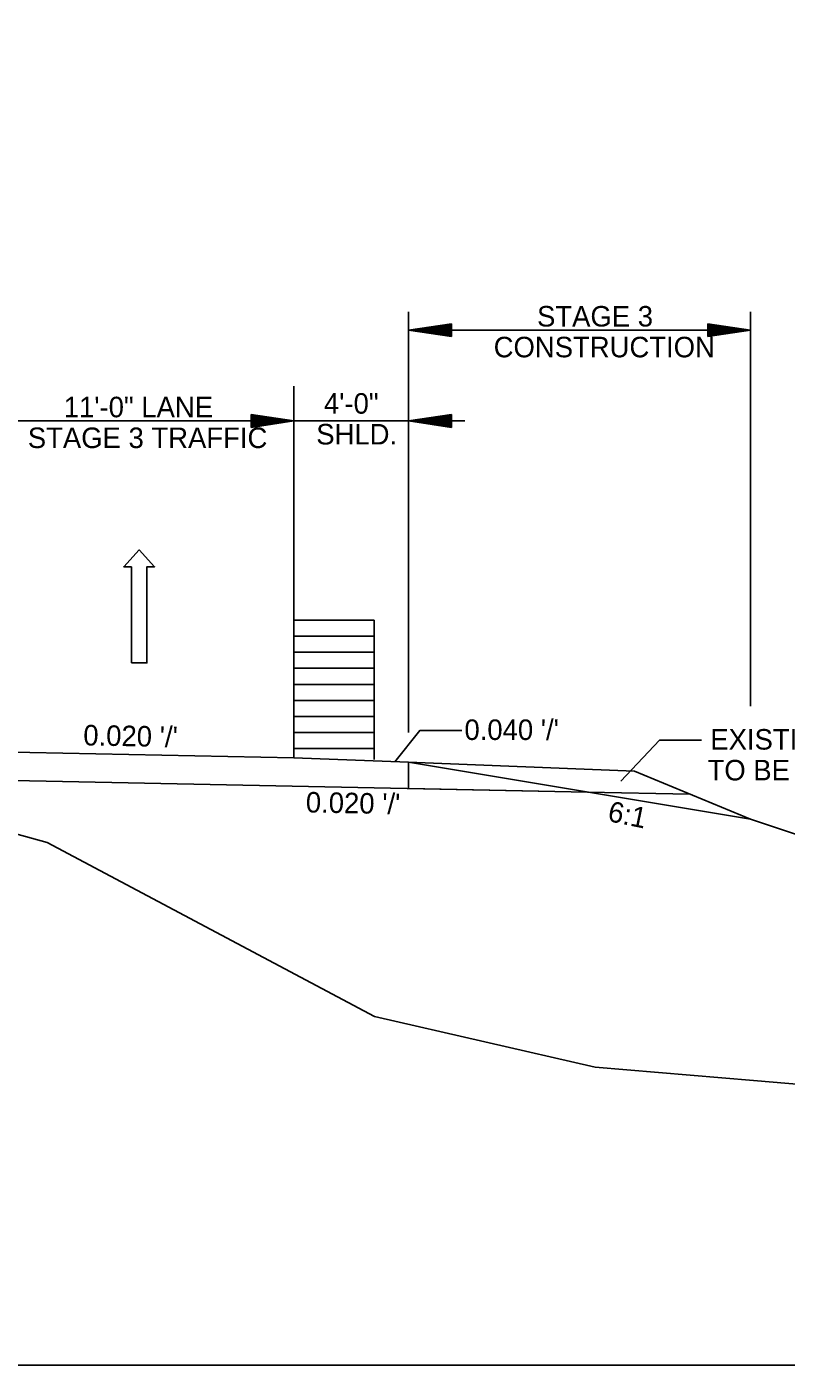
# Model space of a CAD drawing. Extents: x 1807779 to 1818251, y 673292 to 678849.
# Drawn here: x 1813605.8 to 1813872, y 676379.9 to 676849.3 of the extents above; entities that cross this region are included whole.
import ezdxf

# ---------------------------------------------------------------- set-up
doc = ezdxf.new("R2010")
doc.units = 0
for name, color, linetype in [('Default', 7, 'Continuous'), ('Dimensions', 7, 'Continuous'), ('DSN_DRFT_Guideline-No-Plot', 7, 'Continuous'), ('EX_DRIVEWAY', 7, 'Continuous'), ('EX_TERRAIN', 7, 'Continuous'), ('R_MOT', 7, 'Continuous')]:
    doc.layers.add(name, color=color, linetype=linetype)

msp = doc.modelspace()

# ---------------------------------------------------------------- linework, layer by layer
at = {"layer": 'Default'}
for p, q in [((1813699.41, 676641.2), (1813699.41, 676592.98)), ((1813727.53, 676641.2), (1813699.41, 676641.2)), ((1813727.53, 676592.29), (1813727.53, 676641.2)), ((1813727.53, 676635.58), (1813699.41, 676635.58)), ((1813727.53, 676629.95), (1813727.53, 676635.58)), ((1813699.41, 676629.95), (1813727.53, 676629.95)), ((1813699.41, 676624.33), (1813727.53, 676624.33)), ((1813699.41, 676618.7), (1813699.41, 676624.33)), ((1813727.53, 676618.7), (1813699.41, 676618.7)), ((1813699.41, 676613.08), (1813727.53, 676613.08)), ((1813699.41, 676607.45), (1813699.41, 676613.08)), ((1813727.53, 676607.45), (1813699.41, 676607.45)), ((1813727.53, 676601.83), (1813699.41, 676601.83)), ((1813727.53, 676596.2), (1813727.53, 676601.83)), ((1813699.41, 676596.2), (1813727.53, 676596.2)), ((1813739.66, 676591.37), (1813739.66, 676582.17)), ((1813739.66, 676582.17), (1813802.36, 676580.92))]:
    msp.add_line(p, q, dxfattribs=at)
at = {"layer": 'Dimensions'}
for p, q in [((1813739.66, 676723.25), (1813739.66, 676749.35)), ((1813859.54, 676611), (1813859.54, 676749.35)), ((1813754.66, 676745.16), (1813739.66, 676742.91)), ((1813754.66, 676744.78), (1813742.17, 676742.91)), ((1813754.66, 676744.4), (1813744.75, 676742.91)), ((1813754.66, 676744.03), (1813747.24, 676742.91)), ((1813754.66, 676740.66), (1813754.66, 676745.16)), ((1813844.54, 676745.16), (1813859.54, 676742.91)), ((1813844.54, 676740.66), (1813844.54, 676745.16)), ((1813844.54, 676744.78), (1813857.03, 676742.91)), ((1813844.54, 676744.4), (1813854.45, 676742.91)), ((1813844.54, 676744.03), (1813851.95, 676742.91)), ((1813859.54, 676742.91), (1813739.66, 676742.91)), ((1813754.66, 676740.66), (1813739.66, 676742.91)), ((1813754.66, 676741.03), (1813742.17, 676742.91)), ((1813754.66, 676741.42), (1813744.75, 676742.91)), ((1813754.66, 676741.79), (1813747.24, 676742.91)), ((1813754.66, 676743.64), (1813749.79, 676742.91)), ((1813754.66, 676742.18), (1813749.79, 676742.91)), ((1813754.66, 676743.26), (1813752.29, 676742.91)), ((1813754.66, 676742.56), (1813752.29, 676742.91)), ((1813844.54, 676743.64), (1813849.41, 676742.91)), ((1813844.54, 676743.26), (1813846.91, 676742.91)), ((1813844.54, 676740.66), (1813859.54, 676742.91)), ((1813844.54, 676742.18), (1813849.41, 676742.91)), ((1813844.54, 676741.42), (1813854.45, 676742.91)), ((1813844.54, 676741.03), (1813857.03, 676742.91)), ((1813844.54, 676741.79), (1813851.95, 676742.91)), ((1813844.54, 676742.56), (1813846.91, 676742.91)), ((1813699.43, 676601.76), (1813699.43, 676723.25)), ((1813739.66, 676601.76), (1813739.66, 676723.25)), ((1813589.43, 676711.08), (1813648.86, 676711.08)), ((1813589.43, 676711.08), (1813699.43, 676711.08)), ((1813684.43, 676713.33), (1813699.43, 676711.08)), ((1813684.43, 676708.83), (1813684.43, 676713.33)), ((1813684.43, 676712.95), (1813696.93, 676711.08)), ((1813684.43, 676712.57), (1813694.35, 676711.08)), ((1813684.43, 676712.19), (1813691.85, 676711.08)), ((1813684.43, 676711.81), (1813689.31, 676711.08)), ((1813684.43, 676711.43), (1813686.8, 676711.08)), ((1813684.43, 676708.83), (1813699.43, 676711.08)), ((1813684.43, 676710.35), (1813689.31, 676711.08)), ((1813684.43, 676709.58), (1813694.35, 676711.08)), ((1813684.43, 676709.2), (1813696.93, 676711.08)), ((1813684.43, 676709.96), (1813691.85, 676711.08)), ((1813684.43, 676710.72), (1813686.8, 676711.08)), ((1813699.43, 676711.08), (1813759.3, 676711.08)), ((1813754.66, 676713.33), (1813739.66, 676711.08)), ((1813754.66, 676708.83), (1813739.66, 676711.08)), ((1813754.66, 676712.95), (1813742.17, 676711.08)), ((1813754.66, 676709.2), (1813742.17, 676711.08)), ((1813754.66, 676712.57), (1813744.75, 676711.08)), ((1813754.66, 676709.58), (1813744.75, 676711.08)), ((1813754.66, 676712.19), (1813747.24, 676711.08)), ((1813754.66, 676709.96), (1813747.24, 676711.08)), ((1813754.66, 676711.81), (1813749.79, 676711.08)), ((1813754.66, 676710.35), (1813749.79, 676711.08)), ((1813754.66, 676711.43), (1813752.29, 676711.08)), ((1813754.66, 676710.72), (1813752.29, 676711.08)), ((1813754.66, 676708.83), (1813754.66, 676713.33)), ((1813642.46, 676626.19), (1813642.46, 676659.92))]:
    msp.add_line(p, q, dxfattribs=at)
for points in [[(1813642.46, 676626.19), (1813647.86, 676626.19), (1813647.86, 676659.92), (1813650.56, 676659.92), (1813645.16, 676665.84), (1813639.76, 676659.92), (1813642.46, 676659.92)], [(1813734.77, 676591.56), (1813743.57, 676602.48), (1813758.3, 676602.48)], [(1813814.01, 676584.72), (1813827.63, 676599.12), (1813842.37, 676599.12)]]:
    msp.add_lwpolyline(points, dxfattribs=at)
at = {"layer": 'DSN_DRFT_Guideline-No-Plot'}
msp.add_lwpolyline([(1812650.63, 676379.88), (1814300.63, 676379.88), (1814300.63, 677378.94), (1812650.63, 677378.94)], close=True, dxfattribs=at)
at = {"layer": 'EX_DRIVEWAY'}
for p, q in [((1813589.43, 676595.18), (1813699.41, 676592.98)), ((1813699.41, 676592.98), (1813739.66, 676591.37)), ((1813589.43, 676585.18), (1813802.36, 676580.92)), ((1813859.54, 676571.39), (1814149.89, 676474.61))]:
    msp.add_line(p, q, dxfattribs=at)
at = {"layer": 'EX_TERRAIN'}
for p, q in [((1813739.66, 676591.37), (1813818.83, 676588.2)), ((1813818.83, 676588.2), (1813859.54, 676571.39)), ((1813802.36, 676580.92), (1813838.2, 676580.2))]:
    msp.add_line(p, q, dxfattribs=at)
msp.add_lwpolyline([(1812677.73, 676590.75), (1812733.39, 676557.8), (1812876.78, 676502.56), (1812958.07, 676504.7), (1813052.65, 676556.13), (1813143.36, 676593.92), (1813217.94, 676596.07), (1813298.12, 676597.14), (1813458.11, 676595), (1813486.58, 676594.36), (1813514.91, 676590.77), (1813565.47, 676576.34), (1813612.93, 676563.25), (1813727.64, 676502.24), (1813805.09, 676484.4), (1813860.58, 676479.74), (1813917.03, 676474.91), (1814103.84, 676473.94), (1814245.64, 676472.02)], dxfattribs=at)
at = {"layer": 'R_MOT'}
msp.add_line((1813739.66, 676591.37), (1813859.54, 676571.39), dxfattribs=at)

# ---------------------------------------------------------------- texts
at = {"layer": 'Dimensions'}
for s, p in [('STAGE 3 ', (1813784.67, 676744.2)), ('CONSTRUCTION', (1813769.47, 676733.4)), ('4\'-0" ', (1813709.95, 676713.63)), ('11\'-0" LANE', (1813618.72, 676712.37)), ('STAGE 3 TRAFFIC', (1813606.12, 676701.57)), ('SHLD. ', (1813707.26, 676702.83))]:
    msp.add_text(s, height=7.2, dxfattribs=at).set_placement(p)
for s, rotation, p in [("0.020 '/'", 358.8777, (1813625.52, 676597.31)), ("0.040 '/'", 360, (1813759.22, 676599.18)), ('EXISTING WIDENING', 360, (1813845.42, 676595.81)), ('TO BE OBLITERATED', 360, (1813844.46, 676585.01)), ("0.020 '/'", 358.8777, (1813703.55, 676573.79)), ('6:1', 348.3502, (1813809.12, 676570.81))]:
    msp.add_text(s, height=7.2, rotation=rotation, dxfattribs=at).set_placement(p)

doc.saveas('drawing.dxf')
